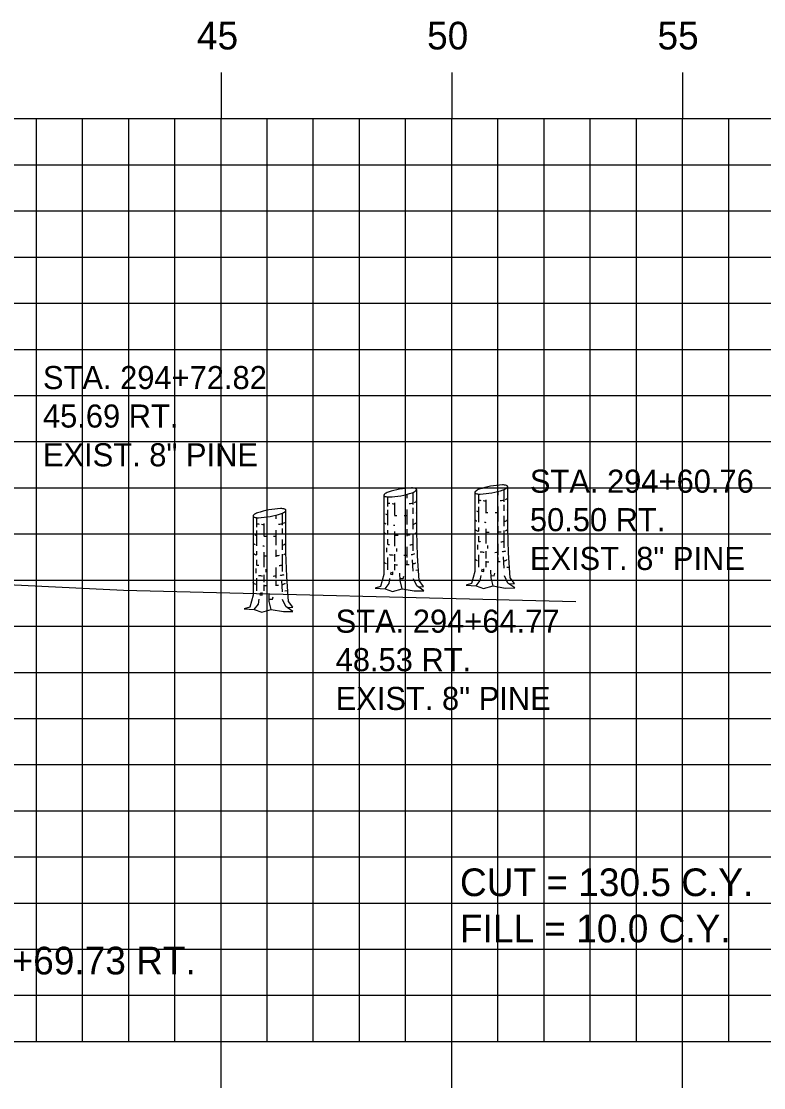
# Model space of a CAD drawing. Extents: x 859352 to 859522, y 366268 to 366378.
# Drawn here: x 859475.8 to 859491.89, y 366306.23 to 366329.35 of the extents above; entities that cross this region are included whole.
import ezdxf

# ---------------------------------------------------------------- set-up
doc = ezdxf.new("R2010")
doc.units = 0
for name, color, linetype in [('ANNOTATION', 7, 'Continuous'), ('D_Drainage_Text', 7, 'Continuous'), ('D_Text_Monospaced', 7, 'Continuous'), ('H_V ANNOTATION', 7, 'Continuous'), ('MAJOR', 7, 'Continuous'), ('MINOR', 7, 'Continuous'), ('S_Roadway_Centerline', 7, 'Continuous'), ('S_Trees_Conifer_NonPay', 7, 'Continuous')]:
    doc.layers.add(name, color=color, linetype=linetype)

msp = doc.modelspace()

# ---------------------------------------------------------------- linework, layer by layer
at = {"layer": 'MAJOR'}
for p, q in [((859480.129, 366328.238), (859480.129, 366327.236)), ((859485.129, 366328.238), (859485.129, 366327.236)), ((859490.129, 366328.238), (859490.129, 366327.236)), ((859365.129, 366327.236), (859505.129, 366327.236)), ((859365.129, 366327.236), (859505.129, 366327.236)), ((859480.129, 366307.236), (859480.129, 366327.236)), ((859485.129, 366307.236), (859485.129, 366327.236)), ((859490.129, 366307.236), (859490.129, 366327.236)), ((859365.129, 366322.236), (859505.129, 366322.236)), ((859365.129, 366317.236), (859505.129, 366317.236)), ((859365.129, 366312.236), (859505.129, 366312.236)), ((859365.129, 366307.236), (859505.129, 366307.236)), ((859365.129, 366307.236), (859505.129, 366307.236)), ((859480.129, 366306.234), (859480.129, 366307.236)), ((859485.129, 366306.234), (859485.129, 366307.236)), ((859490.129, 366306.234), (859490.129, 366307.236))]:
    msp.add_line(p, q, dxfattribs=at)
at = {"layer": 'MINOR'}
for p, q in [((859476.129, 366307.236), (859476.129, 366327.236)), ((859477.129, 366307.236), (859477.129, 366327.236)), ((859478.129, 366307.236), (859478.129, 366327.236)), ((859479.129, 366307.236), (859479.129, 366327.236)), ((859481.129, 366307.236), (859481.129, 366327.236)), ((859482.129, 366307.236), (859482.129, 366327.236)), ((859483.129, 366307.236), (859483.129, 366327.236)), ((859484.129, 366307.236), (859484.129, 366327.236)), ((859486.129, 366307.236), (859486.129, 366327.236)), ((859487.129, 366307.236), (859487.129, 366327.236)), ((859488.129, 366307.236), (859488.129, 366327.236)), ((859489.129, 366307.236), (859489.129, 366327.236)), ((859491.129, 366307.236), (859491.129, 366327.236)), ((859365.129, 366326.236), (859505.129, 366326.236)), ((859365.129, 366325.236), (859505.129, 366325.236)), ((859365.129, 366324.236), (859505.129, 366324.236)), ((859365.129, 366323.236), (859505.129, 366323.236)), ((859365.129, 366321.236), (859505.129, 366321.236)), ((859365.129, 366320.236), (859505.129, 366320.236)), ((859365.129, 366319.236), (859505.129, 366319.236)), ((859365.129, 366318.236), (859505.129, 366318.236)), ((859365.129, 366316.236), (859505.129, 366316.236)), ((859365.129, 366315.236), (859505.129, 366315.236)), ((859365.129, 366314.236), (859505.129, 366314.236)), ((859365.129, 366313.236), (859505.129, 366313.236)), ((859365.129, 366311.236), (859505.129, 366311.236)), ((859365.129, 366310.236), (859505.129, 366310.236)), ((859365.129, 366309.236), (859505.129, 366309.236)), ((859365.129, 366308.236), (859505.129, 366308.236))]:
    msp.add_line(p, q, dxfattribs=at)
at = {"layer": 'S_Roadway_Centerline'}
msp.add_lwpolyline([(859464.006, 366317.706), (859478.018, 366317.015), (859487.818, 366316.774)], dxfattribs=at)
at = {"layer": 'S_Trees_Conifer_NonPay'}
for p, q in [((859484.153, 366319.093), (859484.153, 366319.014)), ((859485.706, 366319.101), (859485.706, 366318.896)), ((859486.125, 366319.156), (859486.125, 366319.078)), ((859483.734, 366319.038), (859483.734, 366318.832)), ((859483.891, 366318.913), (859483.891, 366318.639)), ((859485.863, 366318.977), (859485.863, 366318.703)), ((859486.259, 366318.868), (859486.259, 366318.737)), ((859481.32, 366318.644), (859481.32, 366318.565)), ((859483.734, 366318.759), (859483.734, 366318.428)), ((859484.153, 366318.765), (859484.153, 366318.439)), ((859484.287, 366318.804), (859484.287, 366318.673)), ((859485.706, 366318.823), (859485.706, 366318.492)), ((859486.125, 366318.828), (859486.125, 366318.503)), ((859486.259, 366318.628), (859486.259, 366318.402)), ((859480.901, 366318.589), (859480.901, 366318.384)), ((859481.058, 366318.464), (859481.058, 366318.191)), ((859484.287, 366318.565), (859484.287, 366318.338)), ((859485.706, 366318.378), (859485.706, 366318.299)), ((859486.125, 366318.402), (859486.125, 366318.248)), ((859480.901, 366318.311), (859480.901, 366317.979)), ((859481.32, 366318.316), (859481.32, 366317.99)), ((859481.455, 366318.355), (859481.455, 366318.225)), ((859483.734, 366318.314), (859483.734, 366318.235)), ((859483.891, 366318.286), (859483.891, 366317.967)), ((859484.153, 366318.338), (859484.153, 366318.185)), ((859484.287, 366318.246), (859484.287, 366317.87)), ((859485.706, 366318.185), (859485.706, 366318.075)), ((859485.863, 366318.349), (859485.863, 366318.031)), ((859486.259, 366318.31), (859486.259, 366317.934)), ((859481.455, 366318.116), (859481.455, 366317.889)), ((859483.717, 366317.934), (859483.717, 366317.837)), ((859483.734, 366318.121), (859483.734, 366318.011)), ((859483.932, 366317.923), (859483.932, 366317.853)), ((859484.153, 366317.956), (859484.153, 366317.723)), ((859485.689, 366317.998), (859485.689, 366317.901)), ((859485.904, 366317.986), (859485.904, 366317.917)), ((859486.125, 366318.02), (859486.125, 366317.786)), ((859480.901, 366317.865), (859480.901, 366317.786)), ((859481.058, 366317.837), (859481.058, 366317.519)), ((859481.32, 366317.889), (859481.32, 366317.736)), ((859481.455, 366317.798), (859481.455, 366317.422)), ((859483.734, 366317.723), (859483.734, 366317.455)), ((859483.891, 366317.798), (859483.891, 366317.638)), ((859485.706, 366317.786), (859485.706, 366317.519)), ((859485.863, 366317.861), (859485.863, 366317.702)), ((859486.125, 366317.724), (859486.125, 366317.638)), ((859486.241, 366317.741), (859486.258, 366317.496)), ((859480.884, 366317.485), (859480.884, 366317.388)), ((859480.901, 366317.672), (859480.901, 366317.563)), ((859481.1, 366317.474), (859481.1, 366317.404)), ((859481.32, 366317.508), (859481.32, 366317.274)), ((859483.891, 366317.58), (859483.891, 366317.449)), ((859484.153, 366317.66), (859484.153, 366317.574)), ((859484.269, 366317.677), (859484.286, 366317.432)), ((859484.348, 366317.449), (859484.408, 366317.456)), ((859485.863, 366317.644), (859485.863, 366317.513)), ((859486.32, 366317.513), (859486.38, 366317.519)), ((859480.901, 366317.274), (859480.901, 366317.006)), ((859481.058, 366317.349), (859481.058, 366317.189)), ((859481.436, 366317.229), (859481.453, 366316.983)), ((859481.058, 366317.132), (859481.058, 366317)), ((859481.32, 366317.212), (859481.32, 366317.126)), ((859481.515, 366317), (859481.575, 366317.007))]:
    msp.add_line(p, q, dxfattribs=at)
for points in [[(859483.655, 366319.072), (859483.655, 366317.354), (859483.586, 366317.097), (859483.466, 366317.063), (859483.683, 366317.047), (859483.842, 366316.988), (859484.052, 366317.047), (859484.314, 366317), (859484.52, 366317.006), (859484.369, 366317.109), (859484.297, 366317.262)], [(859484.287, 366319.133), (859484.287, 366319.036), (859484.287, 366318.872)], [(859484.398, 366317.088), (859484.514, 366317.097), (859484.422, 366317.223), (859484.389, 366317.763), (859484.369, 366318.28), (859484.369, 366319.2)], [(859485.627, 366319.135), (859485.627, 366317.418), (859485.558, 366317.161), (859485.438, 366317.127), (859485.655, 366317.11), (859485.814, 366317.052), (859486.024, 366317.11), (859486.286, 366317.063), (859486.492, 366317.069), (859486.341, 366317.172), (859486.269, 366317.326)], [(859486.259, 366319.197), (859486.259, 366319.1), (859486.259, 366318.935)], [(859486.37, 366317.152), (859486.486, 366317.161), (859486.394, 366317.286), (859486.361, 366317.827), (859486.341, 366318.344), (859486.341, 366319.263)], [(859480.823, 366318.623), (859480.823, 366316.905), (859480.753, 366316.649), (859480.634, 366316.614), (859480.85, 366316.598), (859481.01, 366316.54), (859481.219, 366316.598), (859481.482, 366316.551), (859481.688, 366316.557), (859481.536, 366316.66), (859481.464, 366316.813)], [(859481.455, 366318.685), (859481.455, 366318.588), (859481.455, 366318.423)], [(859481.565, 366316.639), (859481.682, 366316.649), (859481.59, 366316.774), (859481.556, 366317.315), (859481.536, 366317.832), (859481.536, 366318.751)], [(859485.786, 366317.473), (859485.775, 366317.429), (859485.825, 366317.418), (859485.825, 366317.479)], [(859483.683, 366317.047), (859483.773, 366317.159), (859483.79, 366317.273)], [(859483.814, 366317.41), (859483.803, 366317.365), (859483.854, 366317.354), (859483.854, 366317.416)], [(859484.052, 366317.047), (859484.007, 366317.223), (859484.001, 366317.387)], [(859484.005, 366317.273), (859484.075, 366317.267), (859484.093, 366317.32)], [(859485.655, 366317.11), (859485.745, 366317.223), (859485.762, 366317.337)], [(859486.024, 366317.11), (859485.979, 366317.286), (859485.973, 366317.451)], [(859485.977, 366317.336), (859486.047, 366317.331), (859486.065, 366317.383)], [(859480.85, 366316.598), (859480.94, 366316.71), (859480.957, 366316.824)], [(859480.982, 366316.961), (859480.97, 366316.916), (859481.021, 366316.905), (859481.021, 366316.967)], [(859481.219, 366316.598), (859481.174, 366316.774), (859481.169, 366316.939)], [(859481.172, 366316.824), (859481.242, 366316.819), (859481.26, 366316.871)]]:
    msp.add_lwpolyline(points, dxfattribs=at)
for centre, radius, start, end in [((859483.674, 366319.071), 0.0186, 160.3798, 174.3267), ((859483.669, 366319.072), 0.0141, 174.3267, 190.3798), ((859483.681, 366319.069), 0.0263, 141.6195, 160.3798), ((859483.718, 366319.04), 0.0729, 130.3798, 141.6195), ((859483.829, 366318.909), 0.245, 108.3946, 130.3798), ((859484.328, 366317.409), 1.825, 100.3798, 108.3946), ((859484.328, 366317.409), 1.825, 92.3651, 100.3798), ((859483.696, 366320.86), 1.825, 280.3798, 288.3946), ((859484.263, 366318.988), 0.245, 70.3798, 92.3651), ((859484.194, 366319.361), 0.245, 288.3946, 310.3798), ((859484.321, 366319.15), 0.0729, 59.1402, 70.3798), ((859484.306, 366319.229), 0.0729, 310.3798, 321.6195), ((859484.344, 366319.19), 0.0263, 40.3798, 59.1402), ((859484.343, 366319.2), 0.0263, 321.6195, 340.3798), ((859484.35, 366319.195), 0.0186, 26.433, 40.3798), ((859484.354, 366319.197), 0.0141, 10.3798, 26.433), ((859484.35, 366319.198), 0.0186, 340.3798, 354.3267), ((859484.354, 366319.197), 0.0141, 354.3267, 10.3798), ((859485.646, 366319.135), 0.0186, 160.3798, 174.3267), ((859485.641, 366319.136), 0.0141, 174.3267, 190.3798), ((859485.641, 366319.136), 0.0141, 190.3798, 206.433), ((859485.653, 366319.133), 0.0263, 141.6195, 160.3798), ((859485.645, 366319.138), 0.0186, 206.433, 220.3798), ((859485.651, 366319.143), 0.0263, 220.3798, 239.1402), ((859485.69, 366319.104), 0.0729, 130.3798, 141.6195), ((859485.675, 366319.183), 0.0729, 239.1402, 250.3798), ((859485.801, 366318.972), 0.245, 108.3946, 130.3798), ((859485.733, 366319.345), 0.245, 250.3798, 272.3651), ((859486.3, 366317.473), 1.825, 100.3798, 108.3946), ((859485.668, 366320.924), 1.825, 272.3651, 280.3798), ((859486.3, 366317.473), 1.825, 92.3651, 100.3798), ((859485.668, 366320.924), 1.825, 280.3798, 288.3946), ((859486.235, 366319.052), 0.245, 70.3798, 92.3651), ((859486.166, 366319.424), 0.245, 288.3946, 310.3798), ((859486.293, 366319.214), 0.0729, 59.1402, 70.3798), ((859486.278, 366319.293), 0.0729, 310.3798, 321.6195), ((859486.316, 366319.254), 0.0263, 40.3798, 59.1402), ((859486.315, 366319.264), 0.0263, 321.6195, 340.3798), ((859486.322, 366319.259), 0.0186, 26.433, 40.3798), ((859486.326, 366319.261), 0.0141, 10.3798, 26.433), ((859486.322, 366319.261), 0.0186, 340.3798, 354.3267), ((859486.326, 366319.261), 0.0141, 354.3267, 10.3798), ((859483.669, 366319.072), 0.0141, 190.3798, 206.433), ((859483.67, 366318.956), 0.0143, 180, 196.0515), ((859483.673, 366319.074), 0.0186, 206.433, 220.3798), ((859483.679, 366319.079), 0.0263, 220.3798, 239.1402), ((859483.703, 366319.119), 0.0729, 239.1402, 250.3798), ((859483.761, 366319.281), 0.245, 250.3798, 272.3651), ((859483.798, 366319.145), 0.245, 254.8461, 261.8968), ((859484.012, 366320.652), 1.767, 261.8968, 262.605), ((859483.696, 366320.86), 1.825, 272.3651, 280.3798), ((859484.012, 366320.652), 1.767, 264.3267, 266.0499), ((859484.012, 366320.652), 1.767, 276.2449, 278.1032), ((859484.227, 366319.145), 0.245, 278.1032, 284.1859), ((859484.227, 366319.145), 0.245, 291.7653, 300), ((859484.312, 366318.997), 0.0738, 300, 311.2506), ((859484.343, 366318.961), 0.0267, 311.2506, 330), ((859484.35, 366318.957), 0.0189, 330, 343.9485), ((859485.642, 366319.02), 0.0143, 180, 196.0515), ((859485.77, 366319.208), 0.245, 254.8461, 261.8968), ((859485.984, 366320.716), 1.767, 261.8968, 262.605), ((859485.984, 366320.716), 1.767, 264.3267, 266.0499), ((859485.984, 366320.716), 1.767, 276.2449, 278.1032), ((859486.199, 366319.208), 0.245, 278.1032, 284.1859), ((859486.199, 366319.208), 0.245, 291.7653, 300), ((859486.284, 366319.06), 0.0738, 300, 311.2506), ((859486.315, 366319.025), 0.0267, 311.2506, 330), ((859486.322, 366319.021), 0.0189, 330, 343.9485), ((859480.841, 366318.623), 0.0186, 160.3798, 174.3267), ((859480.837, 366318.623), 0.0141, 174.3267, 190.3798), ((859480.837, 366318.623), 0.0141, 190.3798, 206.433), ((859480.848, 366318.62), 0.0263, 141.6195, 160.3798), ((859480.841, 366318.625), 0.0186, 206.433, 220.3798), ((859480.847, 366318.63), 0.0263, 220.3798, 239.1402), ((859480.885, 366318.591), 0.0729, 130.3798, 141.6195), ((859480.997, 366318.46), 0.245, 108.3946, 130.3798), ((859481.495, 366316.96), 1.825, 100.3798, 108.3946), ((859480.863, 366320.411), 1.825, 272.3651, 280.3798), ((859481.495, 366316.96), 1.825, 92.3651, 100.3798), ((859480.863, 366320.411), 1.825, 280.3798, 288.3946), ((859481.43, 366318.539), 0.245, 70.3798, 92.3651), ((859481.362, 366318.912), 0.245, 288.3946, 310.3798), ((859481.488, 366318.702), 0.0729, 59.1402, 70.3798), ((859481.473, 366318.781), 0.0729, 310.3798, 321.6195), ((859481.512, 366318.742), 0.0263, 40.3798, 59.1402), ((859481.51, 366318.752), 0.0263, 321.6195, 340.3798), ((859481.518, 366318.747), 0.0186, 26.433, 40.3798), ((859481.522, 366318.749), 0.0141, 10.3798, 26.433), ((859481.517, 366318.749), 0.0186, 340.3798, 354.3267), ((859481.522, 366318.749), 0.0141, 354.3267, 10.3798), ((859483.8, 366318.892), 0.245, 244.3148, 257.5375), ((859484.014, 366320.4), 1.767, 265.8991, 267.5962), ((859484.014, 366320.4), 1.767, 272.7221, 274.4847), ((859484.345, 366318.709), 0.0267, 311.2506, 330), ((859484.352, 366318.705), 0.0189, 330, 343.9485), ((859485.772, 366318.956), 0.245, 244.3148, 257.5375), ((859485.986, 366320.464), 1.767, 265.8991, 267.5962), ((859485.986, 366320.464), 1.767, 272.7221, 274.4847), ((859486.317, 366318.773), 0.0267, 311.2506, 330), ((859486.324, 366318.769), 0.0189, 330, 343.9485), ((859480.838, 366318.507), 0.0143, 180, 196.0515), ((859480.871, 366318.67), 0.0729, 239.1402, 250.3798), ((859480.928, 366318.832), 0.245, 250.3798, 272.3651), ((859480.965, 366318.696), 0.245, 254.8461, 261.8968), ((859481.18, 366320.203), 1.767, 261.8968, 262.605), ((859481.18, 366320.203), 1.767, 264.3267, 266.0499), ((859481.18, 366320.203), 1.767, 276.2449, 278.1032), ((859481.394, 366318.696), 0.245, 278.1032, 284.1859), ((859481.394, 366318.696), 0.245, 291.7653, 300), ((859481.48, 366318.548), 0.0738, 300, 311.2506), ((859481.511, 366318.513), 0.0267, 311.2506, 330), ((859481.518, 366318.509), 0.0189, 330, 343.9485), ((859483.67, 366318.49), 0.0143, 180, 196.0515), ((859483.675, 366318.491), 0.0189, 196.0515, 210), ((859483.681, 366318.495), 0.0267, 210, 228.7494), ((859483.712, 366318.531), 0.0738, 228.7494, 240), ((859483.798, 366318.679), 0.245, 240, 246.7914), ((859483.798, 366318.679), 0.245, 254.8461, 257.5454), ((859484.012, 366320.186), 1.767, 265.2285, 266.1325), ((859484.227, 366318.679), 0.245, 284.1859, 300), ((859484.312, 366318.531), 0.0738, 300, 311.2506), ((859484.343, 366318.495), 0.0267, 311.2506, 330), ((859484.35, 366318.491), 0.0189, 330, 343.9485), ((859485.642, 366318.554), 0.0143, 180, 196.0515), ((859485.647, 366318.555), 0.0189, 196.0515, 210), ((859485.653, 366318.559), 0.0267, 210, 228.7494), ((859485.684, 366318.594), 0.0738, 228.7494, 240), ((859485.77, 366318.742), 0.245, 240, 246.7914), ((859485.77, 366318.742), 0.245, 254.8461, 257.5454), ((859485.984, 366320.25), 1.767, 265.2285, 266.1325), ((859486.199, 366318.742), 0.245, 284.1859, 300), ((859486.284, 366318.594), 0.0738, 300, 311.2506), ((859486.315, 366318.559), 0.0267, 311.2506, 330), ((859486.322, 366318.555), 0.0189, 330, 343.9485), ((859480.967, 366318.444), 0.245, 244.3148, 257.5375), ((859481.182, 366319.951), 1.767, 265.8991, 267.5962), ((859481.182, 366319.951), 1.767, 272.7221, 274.4847), ((859481.513, 366318.26), 0.0267, 311.2506, 330), ((859481.519, 366318.256), 0.0189, 330, 343.9485), ((859483.67, 366318.279), 0.0143, 180, 196.0515), ((859483.675, 366318.28), 0.0189, 196.0515, 210), ((859483.682, 366318.284), 0.0267, 210, 228.7494), ((859483.713, 366318.319), 0.0738, 228.7494, 240), ((859483.798, 366318.467), 0.245, 240, 254.9514), ((859484.013, 366319.975), 1.767, 266.0429, 268.5525), ((859484.013, 366319.975), 1.767, 274.5361, 277.0026), ((859484.227, 366318.467), 0.245, 292.1924, 300), ((859484.313, 366318.319), 0.0738, 300, 311.2506), ((859484.344, 366318.284), 0.0267, 311.2506, 330), ((859484.35, 366318.28), 0.0189, 330, 343.9485), ((859485.642, 366318.342), 0.0143, 180, 196.0515), ((859485.647, 366318.344), 0.0189, 196.0515, 210), ((859485.654, 366318.348), 0.0267, 210, 228.7494), ((859485.685, 366318.383), 0.0738, 228.7494, 240), ((859485.77, 366318.531), 0.245, 240, 254.9514), ((859485.985, 366320.038), 1.767, 266.0429, 268.5525), ((859485.985, 366320.038), 1.767, 274.5361, 277.0026), ((859486.199, 366318.531), 0.245, 292.1924, 300), ((859486.285, 366318.383), 0.0738, 300, 311.2506), ((859486.316, 366318.348), 0.0267, 311.2506, 330), ((859486.322, 366318.344), 0.0189, 330, 343.9485), ((859480.838, 366318.041), 0.0143, 180, 196.0515), ((859480.842, 366318.043), 0.0189, 196.0515, 210), ((859480.849, 366318.046), 0.0267, 210, 228.7494), ((859480.88, 366318.082), 0.0738, 228.7494, 240), ((859480.965, 366318.23), 0.245, 240, 246.7914), ((859480.965, 366318.23), 0.245, 254.8461, 257.5454), ((859481.18, 366319.737), 1.767, 265.2285, 266.1325), ((859481.394, 366318.23), 0.245, 284.1859, 300), ((859481.48, 366318.082), 0.0738, 300, 311.2506), ((859481.511, 366318.046), 0.0267, 311.2506, 330), ((859481.518, 366318.043), 0.0189, 330, 343.9485), ((859483.797, 366318.248), 0.245, 254.9814, 261.8968), ((859484.012, 366319.755), 1.767, 261.8968, 262.45), ((859484.012, 366319.755), 1.767, 276.7966, 278.1032), ((859484.226, 366318.248), 0.245, 278.1032, 284.3207), ((859485.769, 366318.311), 0.245, 254.9814, 261.8968), ((859485.984, 366319.819), 1.767, 261.8968, 262.45), ((859485.984, 366319.819), 1.767, 276.7966, 278.1032), ((859486.198, 366318.311), 0.245, 278.1032, 284.3207), ((859480.838, 366317.83), 0.0143, 180, 196.0515), ((859480.842, 366317.831), 0.0189, 196.0515, 210), ((859480.849, 366317.835), 0.0267, 210, 228.7494), ((859480.88, 366317.87), 0.0738, 228.7494, 240), ((859480.965, 366318.018), 0.245, 240, 254.9514), ((859481.18, 366319.526), 1.767, 266.0429, 268.5525), ((859481.18, 366319.526), 1.767, 274.5361, 277.0026), ((859481.395, 366318.018), 0.245, 292.1924, 300), ((859481.48, 366317.87), 0.0738, 300, 311.2506), ((859481.511, 366317.835), 0.0267, 311.2506, 330), ((859481.518, 366317.831), 0.0189, 330, 343.9485), ((859483.67, 366317.842), 0.0143, 180, 196.0515), ((859484.012, 366319.538), 1.767, 262.2622, 265.0496), ((859484.012, 366319.538), 1.767, 272.6293, 274.5612), ((859484.012, 366319.538), 1.767, 277.63, 278.1032), ((859484.226, 366318.031), 0.245, 278.1032, 294.6056), ((859485.642, 366317.906), 0.0143, 180, 196.0515), ((859485.641, 366317.7), 0.0143, 180, 196.0515), ((859485.645, 366317.701), 0.0189, 196.0515, 210), ((859485.652, 366317.705), 0.0267, 210, 228.7494), ((859485.683, 366317.741), 0.0738, 228.7494, 240), ((859485.984, 366319.602), 1.767, 262.2622, 265.0496), ((859485.984, 366319.602), 1.767, 272.6293, 274.5612), ((859485.984, 366319.602), 1.767, 277.63, 278.1032), ((859486.198, 366318.094), 0.245, 278.1032, 294.6056), ((859480.965, 366317.799), 0.245, 254.9814, 261.8968), ((859481.179, 366319.307), 1.767, 261.8968, 262.45), ((859481.179, 366319.307), 1.767, 276.7966, 278.1032), ((859481.394, 366317.799), 0.245, 278.1032, 284.3207), ((859483.669, 366317.637), 0.0143, 180, 196.0515), ((859483.673, 366317.638), 0.0189, 196.0515, 210), ((859483.68, 366317.642), 0.0267, 210, 228.7494), ((859483.711, 366317.677), 0.0738, 228.7494, 240), ((859483.797, 366317.825), 0.245, 240, 249.1675), ((859484.011, 366319.333), 1.767, 266.0862, 268.2187), ((859484.011, 366319.333), 1.767, 274.2776, 276.3006), ((859484.226, 366317.825), 0.245, 284.0684, 300), ((859484.311, 366317.677), 0.0738, 300, 302.05), ((859485.769, 366317.889), 0.245, 240, 249.1675), ((859485.983, 366319.396), 1.767, 266.0862, 268.2187), ((859485.983, 366319.396), 1.767, 274.2776, 276.3006), ((859486.198, 366317.889), 0.245, 284.0684, 300), ((859486.283, 366317.741), 0.0738, 300, 302.05), ((859480.837, 366317.393), 0.0143, 180, 196.0515), ((859481.179, 366319.089), 1.767, 262.2622, 265.0496), ((859481.179, 366319.089), 1.767, 272.6293, 274.5612), ((859481.179, 366319.089), 1.767, 277.63, 278.1032), ((859481.394, 366317.582), 0.245, 278.1032, 294.6056), ((859480.836, 366317.188), 0.0143, 180, 196.0515), ((859480.841, 366317.189), 0.0189, 196.0515, 210), ((859480.848, 366317.193), 0.0267, 210, 228.7494), ((859480.879, 366317.228), 0.0738, 228.7494, 240), ((859480.964, 366317.376), 0.245, 240, 249.1675), ((859481.179, 366318.884), 1.767, 266.0862, 268.2187), ((859481.179, 366318.884), 1.767, 274.2776, 276.3006), ((859481.393, 366317.376), 0.245, 284.0684, 300), ((859481.479, 366317.228), 0.0738, 300, 302.05)]:
    msp.add_arc(centre, radius, start, end, dxfattribs=at)

# ---------------------------------------------------------------- texts
at = {"layer": 'ANNOTATION'}
for s, p in [('CUT = 130.5 C.Y.', (859485.306, 366310.386)), ('FILL = 10.0 C.Y.', (859485.306, 366309.384))]:
    msp.add_text(s, height=0.6, dxfattribs=at).set_placement(p)
at = {"layer": 'D_Drainage_Text'}
msp.add_text('STA. 294+57.00 RT. TO STA. 294+69.73 RT.', height=0.6, dxfattribs=at).set_placement((859463.35, 366308.689))
at = {"layer": 'D_Text_Monospaced'}
for s, height, p in [('STA. 294+72.82', 0.49998, (859476.271, 366321.375)), ('45.69 RT.', 0.5, (859476.271, 366320.541)), ('EXIST. 8" PINE', 0.49998, (859476.271, 366319.701)), ('STA. 294+60.76', 0.49998, (859486.821, 366319.129)), ('50.50 RT.', 0.5, (859486.821, 366318.295)), ('EXIST. 8" PINE', 0.49998, (859486.821, 366317.455)), ('STA. 294+64.77', 0.49998, (859482.613, 366316.095)), ('48.53 RT.', 0.5, (859482.613, 366315.261)), ('EXIST. 8" PINE', 0.49998, (859482.613, 366314.421))]:
    msp.add_text(s, height=height, dxfattribs=at).set_placement(p)
at = {"layer": 'H_V ANNOTATION'}
for s, p in [('45', (859479.608, 366328.736)), ('50', (859484.594, 366328.736)), ('55', (859489.586, 366328.736))]:
    msp.add_text(s, height=0.6, dxfattribs=at).set_placement(p)

doc.saveas('drawing.dxf')
